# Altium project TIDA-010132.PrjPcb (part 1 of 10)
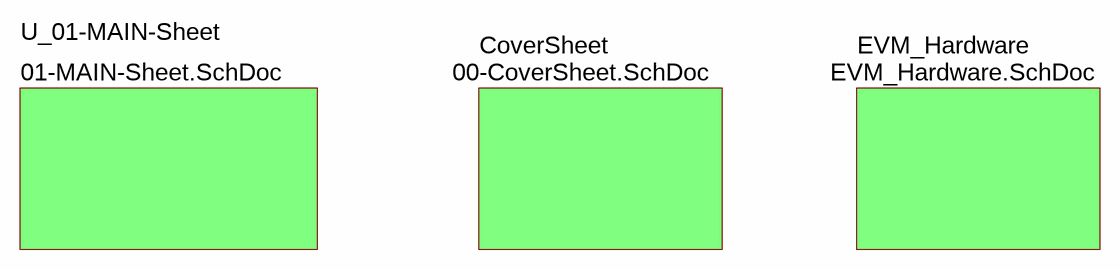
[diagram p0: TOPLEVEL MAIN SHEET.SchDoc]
CopyrightYear: 2018; PCB_Layout: Avinash; PCB_Rev: E1; PRJ_Customer: Public Release; PRJ_Engineer: Sankar Sadasivam; PRJ_Number: TIDA-010132; PRJ_Title: TIDA-010132; SCH_Rev: E1; TechSupport: http://www.ti.com/support; TID: 010132
32 sheets, 1754 parts. Net scope: flat (ports and power ports of the same name join across sheets).
Board file: TIDA-010132.PcbDoc
Sheets:
  TOPLEVEL MAIN SHEET.SchDoc
    U_01-MAIN-Sheet = 01-MAIN-Sheet.SchDoc
      FMC INTERFACE SHEET = FMC INTERFACE SHEET.SchDoc
      AFE1 = AFE1.SchDoc
        AFE1-RX-INPUTS. = AFE1-RX-INPUTS.SchDoc
        AFE1-TX-OUTPUTS = AFE1-TX-OUTPUTS.SchDoc
        AFE1-LMX2594 = AFE1-LMX2594.SchDoc
        AFE1-POWER = AFE1-POWER.SchDoc
        AFE1-SERDES = AFE1-SERDES.SchDoc
        AFE1-RX-TX-INTERFACE. = AFE1-RX-TX-INTERFACE.SchDoc
        AFE1-GROUND = AFE1-GROUND.SchDoc
        AFE1-PROGRAMMING INTERFACE = AFE1-PROGRAMMING INTERFACE.SchDoc
        AFE1-GPIOs = AFE1-GPIOs.SchDoc
      CLOCK MAIN = CLOCK MAIN SHEET.SchDoc
        CLOCK MAIN POWER = CLOCK MAIN POWER.SchDoc
        CLOCK BUFFER = CLOCK BUFFER.SchDoc
      POWER TREE. = POWER TREE.SchDoc
        POWER MAIN SHEET1 = POWER MAIN SHEET1.SchDoc
        POWER MAIN SHEET2 = POWER MAIN SHEET2.SchDoc
      USB INTERFACE = USB INTERFACE SHEET.SchDoc
      AFE2 = AFE2.SchDoc
        AFE2-SERDES = AFE2-SERDES.SchDoc
        AFE2-PROGRAMMING INTERFACE = AFE2-PROGRAMMING INTERFACE.SchDoc
        AFE2-GPIOs = AFE2-GPIOs.SchDoc
        AFE2-RX-INPUTS = AFE2-RX-INPUTS.SchDoc
        AFE2-TX-OUTPUTS = AFE2-TX-OUTPUTS.SchDoc
        AFE2-LMX2594 = AFE2-LMX2594.SchDoc
        AFE2-POWER = AFE2-POWER.SchDoc
        AFE2-RX-TX-INTERFACE = AFE2-RX-TX-INTERFACE.SchDoc
        AFE2-GROUND = AFE2-GROUND.SchDoc
    CoverSheet = 00-CoverSheet.SchDoc
    EVM_Hardware = EVM_Hardware.SchDoc

## Sheet TOPLEVEL MAIN SHEET.SchDoc
size 431 x 279 mm; Date: Not shown in title block; ApprovedBy: Not shown in title block; CheckedBy: Not shown in title block; Author: Not shown in title block; CompanyName: Not shown in title block; DrawnBy: Avinash N; Engineer: Not shown in title block; Organization: Not shown in title block; Address1: Not shown in title block; Address2: Not shown in title block; Address3: Not shown in title block; Address4: Not shown in title block; DocumentNumber: 1; Revision: Use project parameter SCH_Rev; SheetNumber: 2; SheetTotal: 32; PageSetup: Record=PageOptions¦CenterHorizontal=True¦CenterVertical=True¦PrintScale=1.00¦XCorrection=1.00¦YCorrection=1.00¦PrintKind=0¦BorderSize=5000000¦LeftOffset=0¦BottomOffset=0¦Orientation=2¦PaperLength=1000¦PaperWidth=1000¦Scale=100¦PaperSource=15¦PrintQuality=600¦MediaType=1¦DitherType=10¦PaperKind=Letter¦PrintScaleMode=1

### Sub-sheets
CoverSheet = 00-CoverSheet.SchDoc: no entries
EVM_Hardware = EVM_Hardware.SchDoc: no entries
U_01-MAIN-Sheet = 01-MAIN-Sheet.SchDoc: no entries

## Sheet 01-MAIN-Sheet.SchDoc
size 558 x 431 mm; Date: Not shown in title block; ApprovedBy: Not shown in title block; CheckedBy: Not shown in title block; Author: Not shown in title block; CompanyName: Not shown in title block; DrawnBy: Avinash N; Engineer: Not shown in title block; Organization: Not shown in title block; Address1: Not shown in title block; Address2: Not shown in title block; Address3: Not shown in title block; Address4: Not shown in title block; DocumentNumber: 1; Revision: Use project parameter SCH_Rev; SheetNumber: 3; SheetTotal: 32; PageSetup: Record=PageOptions¦CenterHorizontal=True¦CenterVertical=True¦PrintScale=1.00¦XCorrection=1.00¦YCorrection=1.00¦PrintKind=0¦BorderSize=5000000¦LeftOffset=0¦BottomOffset=0¦Orientation=2¦PaperLength=1000¦PaperWidth=1000¦Scale=100¦PaperSource=15¦PrintQuality=600¦MediaType=1¦DitherType=10¦PaperKind=Letter¦PrintScaleMode=1
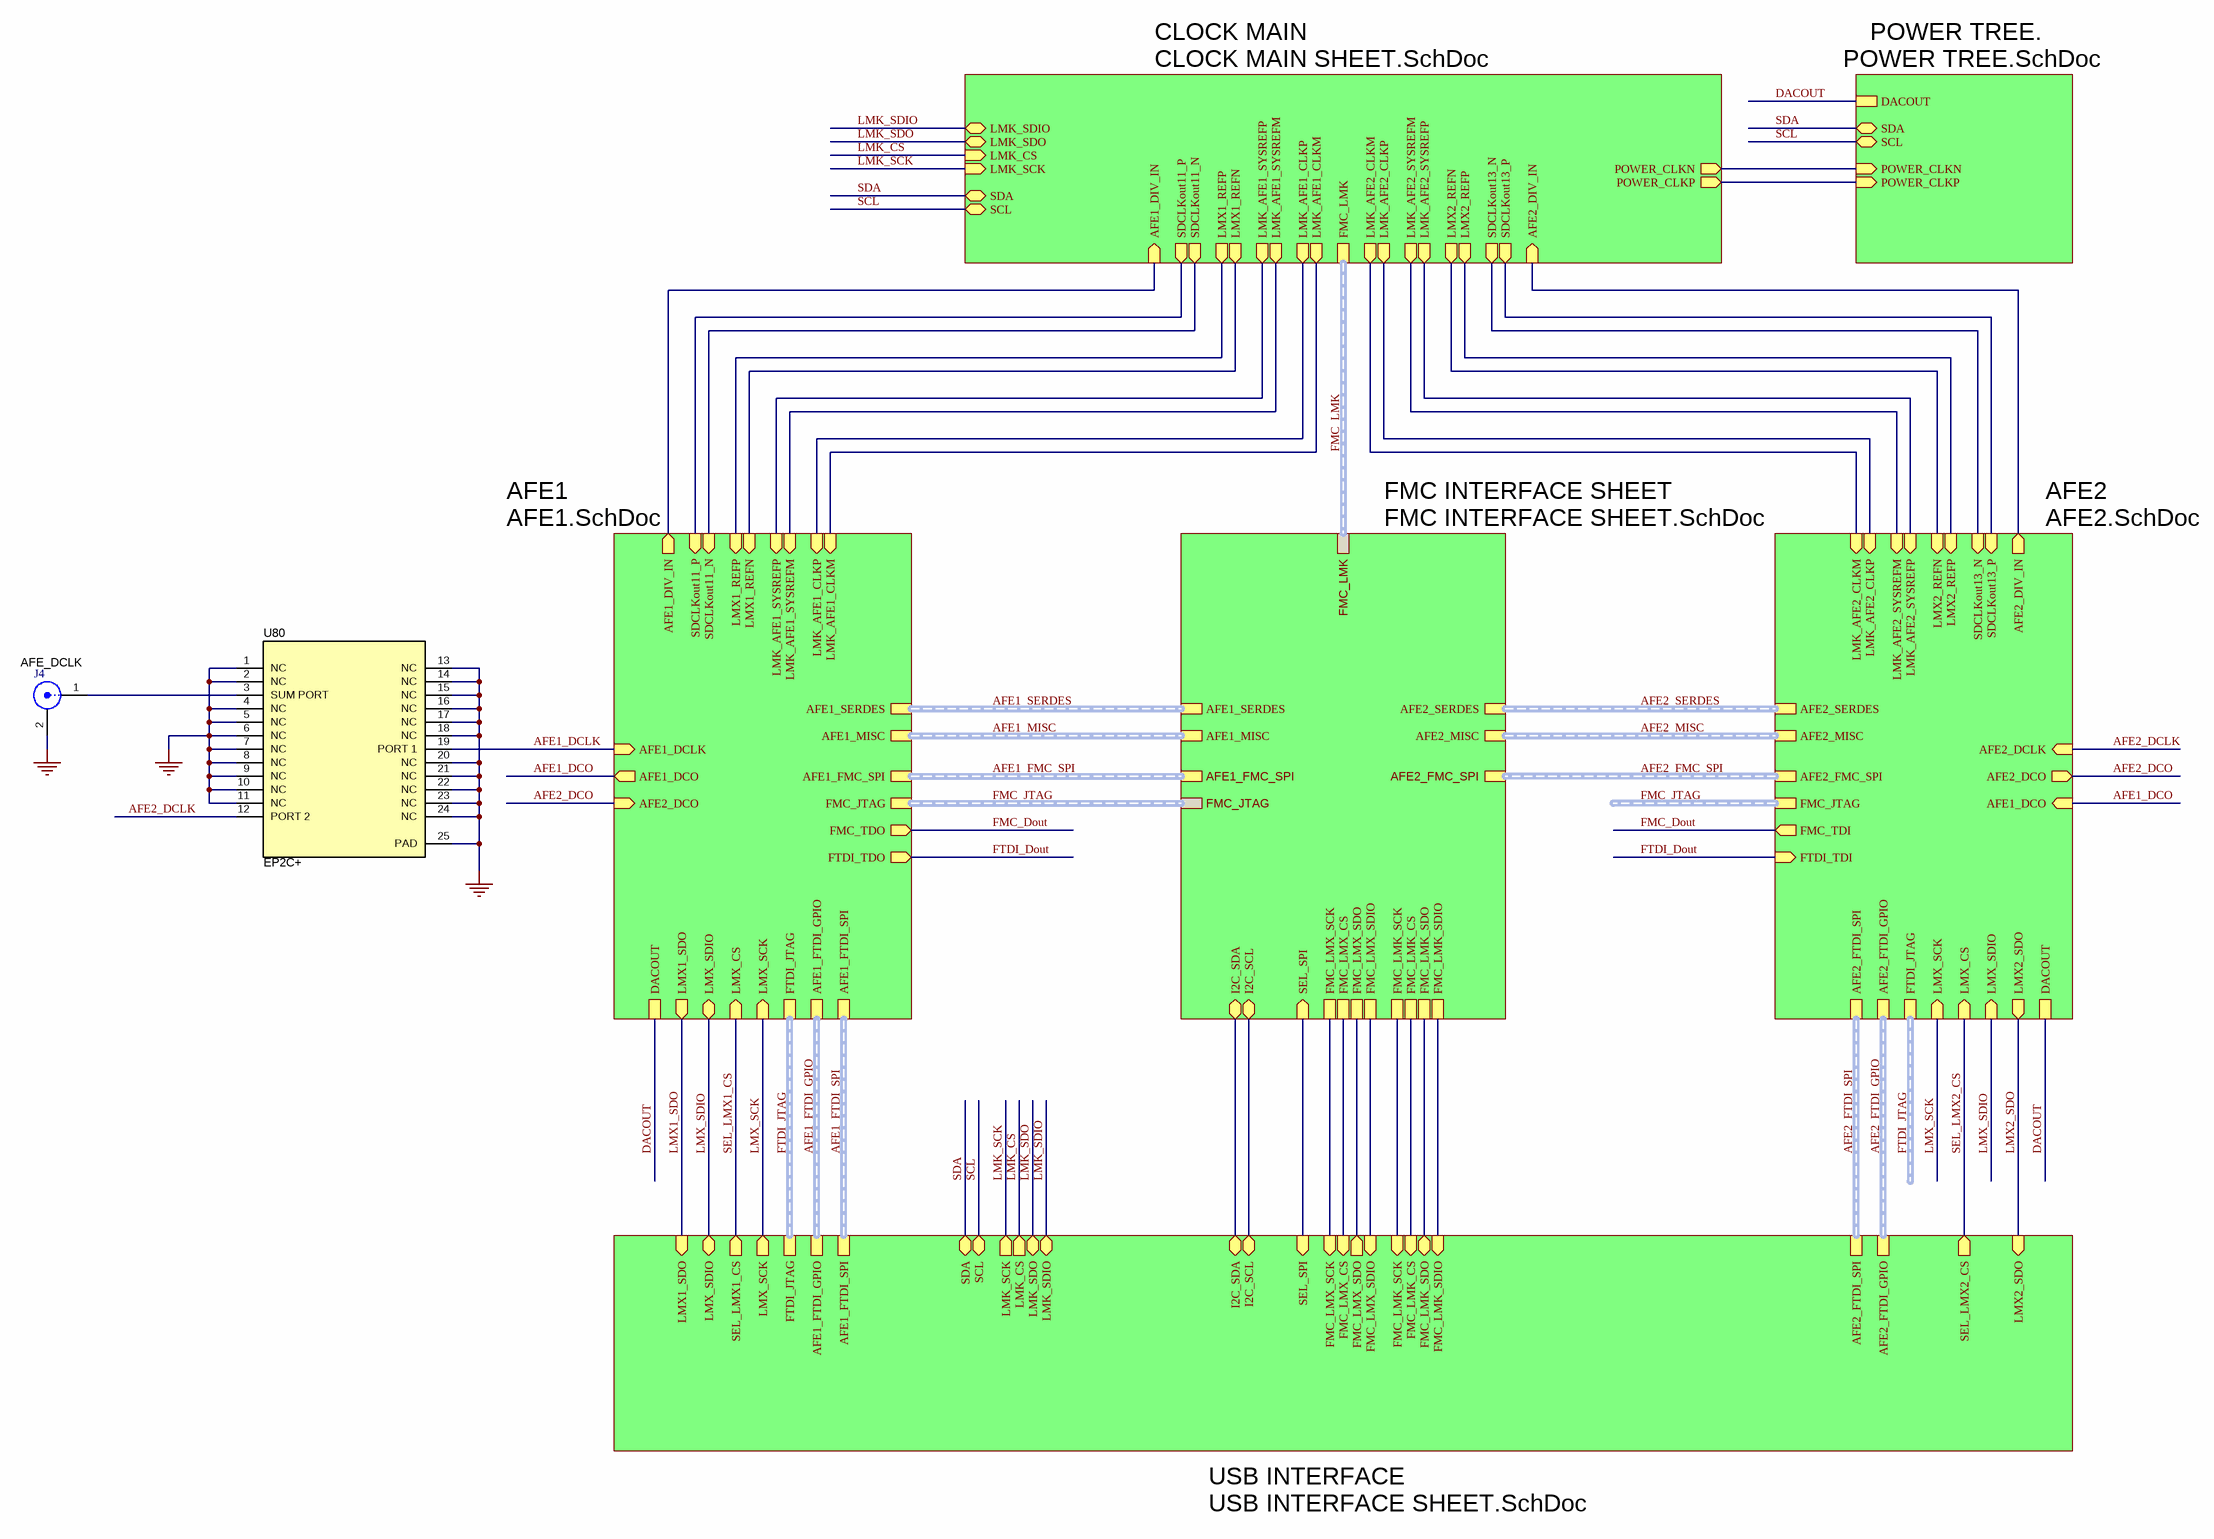
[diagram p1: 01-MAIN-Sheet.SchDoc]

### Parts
J4  AFE_DCLK  [Molex_0853050232]
U80  EP2C+  [DG1847]

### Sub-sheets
AFE1 = AFE1.SchDoc: AFE1_FTDI_SPI (harness AFE1_FTDI_SPI), AFE1_FTDI_GPIO (harness AFE1_FTDI_GPIO), FTDI_JTAG (harness FTDI_JTAG), FMC_JTAG (harness FMC_JTAG), LMX_CS (in), LMX_SCK (in), LMX1_SDO (out), DACOUT, AFE1_FMC_SPI (harness AFE1_FMC_SPI), FTDI_TDO (out), FMC_TDO (out), AFE1_SERDES (harness AFE1_SERDES), AFE1_MISC (harness AFE1_MISC), LMX_SDIO (bidir), LMK_AFE1_CLKP (in), LMK_AFE1_CLKM (in), LMK_AFE1_SYSREFP (in), LMK_AFE1_SYSREFM (in), LMX1_REFN (in), LMX1_REFP (in), SDCLKout11_P (in), SDCLKout11_N (in), AFE1_DIV_IN (out), AFE1_DCLK (in), AFE2_DCO (in), AFE1_DCO (out)
AFE2 = AFE2.SchDoc: AFE2_FTDI_GPIO (harness AFE2_FTDI_GPIO), FMC_JTAG (harness FMC_JTAG), AFE2_FTDI_SPI (harness AFE2_FTDI_SPI), FTDI_JTAG (harness FTDI_JTAG), LMX_SCK (in), LMX_CS (in), LMX_SDIO (in), DACOUT, AFE2_FMC_SPI (harness AFE2_FMC_SPI), LMX2_SDO (out), FTDI_TDI (in), AFE2_MISC (harness AFE2_MISC), AFE2_SERDES (harness AFE2_SERDES), FMC_TDI (out), LMK_AFE2_CLKM (in), LMK_AFE2_CLKP (in), LMK_AFE2_SYSREFM (in), LMK_AFE2_SYSREFP (in), LMX2_REFP (in), LMX2_REFN (in), SDCLKout13_P (in), SDCLKout13_N (in), AFE2_DIV_IN (out), AFE2_DCLK (in), AFE2_DCO (out), AFE1_DCO (in)
CLOCK MAIN = CLOCK MAIN SHEET.SchDoc: AFE1_DIV_IN (in), AFE2_DIV_IN (in), FMC_LMK (harness FMC_LMK), SDA (bidir), SCL (bidir), LMK_SCK (in), LMK_CS (in), LMK_SDIO (bidir), LMK_SDO (bidir), POWER_CLKN (out), POWER_CLKP (out), LMK_AFE1_CLKM (out), LMK_AFE1_CLKP (out), LMX1_REFP (out), LMX1_REFN (out), SDCLKout11_N (out), SDCLKout11_P (out), LMK_AFE2_CLKM (out), LMK_AFE2_CLKP (out), LMK_AFE2_SYSREFP (out), LMK_AFE2_SYSREFM (out), LMX2_REFN (out), LMX2_REFP (out), SDCLKout13_P (out), SDCLKout13_N (out), LMK_AFE1_SYSREFM (out), LMK_AFE1_SYSREFP (out)
FMC INTERFACE SHEET = FMC INTERFACE SHEET.SchDoc: FMC_JTAG (harness FMC_JTAG), FMC_LMK (harness FMC_LMK), AFE1_FMC_SPI (harness AFE1_FMC_SPI), AFE2_FMC_SPI (harness AFE2_FMC_SPI), AFE1_MISC (harness AFE1_MISC), AFE1_SERDES (harness AFE1_SERDES), AFE2_SERDES (harness AFE2_SERDES), AFE2_MISC (harness AFE2_MISC), I2C_SDA (bidir), I2C_SCL (bidir), FMC_LMX_SCK, FMC_LMX_SDIO, FMC_LMX_CS, FMC_LMK_SCK, FMC_LMK_SDO, FMC_LMK_SDIO, FMC_LMK_CS, FMC_LMX_SDO, SEL_SPI (in)
POWER TREE. = POWER TREE.SchDoc: DACOUT, POWER_CLKN (in), POWER_CLKP (in), SDA (bidir), SCL (bidir)
USB INTERFACE = USB INTERFACE SHEET.SchDoc: FMC_LMK_SCK (in), SDA (bidir), SCL (bidir), LMX_SCK (out), FMC_LMX_SDIO (in), LMX_SDIO (bidir), FMC_LMX_CS (in), FMC_LMX_SCK (in), LMX2_SDO (in), LMX1_SDO (in), FMC_LMX_SDO (out), AFE2_FTDI_SPI (harness AFE2_FTDI_SPI), AFE1_FTDI_SPI (harness AFE1_FTDI_SPI), FTDI_JTAG (harness FTDI_JTAG), AFE1_FTDI_GPIO (harness AFE1_FTDI_GPIO), AFE2_FTDI_GPIO (harness AFE2_FTDI_GPIO), LMK_CS (out), LMK_SDIO (bidir), LMK_SDO (bidir), LMK_SCK (out), FMC_LMK_CS (in), FMC_LMK_SDIO (in), FMC_LMK_SDO (bidir), I2C_SCL (bidir), I2C_SDA (bidir), SEL_LMX2_CS (out), SEL_SPI (in), SEL_LMX1_CS (out)

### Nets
GND: J4.2 U80.1(NC) U80.2(NC) U80.4(NC) U80.5(NC) U80.6(NC) U80.7(NC) U80.8(NC) U80.9(NC) U80.10(NC) U80.11(NC) U80.13(NC) U80.14(NC) U80.15(NC) U80.16(NC) U80.17(NC) U80.18(NC) U80.20(NC) U80.21(NC) U80.22(NC) U80.23(NC) U80.24(NC) U80.25(PAD)
AFE1_DCLK: U80.19(PORT_1) ; sheet AFE1/AFE1_DCLK
AFE1_DCO: sheet AFE1/AFE1_DCO, sheet AFE2/AFE1_DCO
AFE2_DCLK: U80.12(PORT_2) ; sheet AFE2/AFE2_DCLK
AFE2_DCO: sheet AFE1/AFE2_DCO, sheet AFE2/AFE2_DCO
DACOUT: sheet AFE1/DACOUT, sheet POWER TREE./DACOUT, sheet AFE2/DACOUT
FMC_Dout: sheet AFE1/FMC_TDO, sheet AFE2/FMC_TDI
FTDI_Dout: sheet AFE1/FTDI_TDO, sheet AFE2/FTDI_TDI
LMK_CS: sheet CLOCK MAIN/LMK_CS, sheet USB INTERFACE/LMK_CS
LMK_SCK: sheet CLOCK MAIN/LMK_SCK, sheet USB INTERFACE/LMK_SCK
LMK_SDIO: sheet CLOCK MAIN/LMK_SDIO, sheet USB INTERFACE/LMK_SDIO
LMK_SDO: sheet CLOCK MAIN/LMK_SDO, sheet USB INTERFACE/LMK_SDO
LMX1_SDO: sheet AFE1/LMX1_SDO, sheet USB INTERFACE/LMX1_SDO
LMX2_SDO: sheet USB INTERFACE/LMX2_SDO, sheet AFE2/LMX2_SDO
LMX_SCK: sheet AFE1/LMX_SCK, sheet USB INTERFACE/LMX_SCK, sheet AFE2/LMX_SCK
LMX_SDIO: sheet AFE1/LMX_SDIO, sheet USB INTERFACE/LMX_SDIO, sheet AFE2/LMX_SDIO
SCL: sheet CLOCK MAIN/SCL, sheet POWER TREE./SCL, sheet USB INTERFACE/SCL
SDA: sheet CLOCK MAIN/SDA, sheet POWER TREE./SDA, sheet USB INTERFACE/SDA
SEL_LMX1_CS: sheet AFE1/LMX_CS, sheet USB INTERFACE/SEL_LMX1_CS
SEL_LMX2_CS: sheet USB INTERFACE/SEL_LMX2_CS, sheet AFE2/LMX_CS
NetJ4_1: J4.1 U80.3(SUM_PORT)
(unnamed): sheet FMC INTERFACE SHEET/I2C_SDA, sheet USB INTERFACE/I2C_SDA
(unnamed): sheet FMC INTERFACE SHEET/I2C_SCL, sheet USB INTERFACE/I2C_SCL  [a separate net that carries the same name]
(unnamed): sheet FMC INTERFACE SHEET/FMC_LMX_SCK, sheet USB INTERFACE/FMC_LMX_SCK  [a separate net that carries the same name]
(unnamed): sheet FMC INTERFACE SHEET/FMC_LMX_SDIO, sheet USB INTERFACE/FMC_LMX_SDIO  [a separate net that carries the same name]
(unnamed): sheet FMC INTERFACE SHEET/FMC_LMX_CS, sheet USB INTERFACE/FMC_LMX_CS  [a separate net that carries the same name]
(unnamed): sheet FMC INTERFACE SHEET/FMC_LMK_SCK, sheet USB INTERFACE/FMC_LMK_SCK  [a separate net that carries the same name]
(unnamed): sheet FMC INTERFACE SHEET/FMC_LMK_SDO, sheet USB INTERFACE/FMC_LMK_SDO  [a separate net that carries the same name]
(unnamed): sheet FMC INTERFACE SHEET/FMC_LMK_SDIO, sheet USB INTERFACE/FMC_LMK_SDIO  [a separate net that carries the same name]
(unnamed): sheet FMC INTERFACE SHEET/FMC_LMK_CS, sheet USB INTERFACE/FMC_LMK_CS  [a separate net that carries the same name]
(unnamed): sheet FMC INTERFACE SHEET/FMC_LMX_SDO, sheet USB INTERFACE/FMC_LMX_SDO  [a separate net that carries the same name]
(unnamed): sheet FMC INTERFACE SHEET/SEL_SPI, sheet USB INTERFACE/SEL_SPI  [a separate net that carries the same name]
(unnamed): sheet AFE1/LMK_AFE1_CLKP, sheet CLOCK MAIN/LMK_AFE1_CLKP  [a separate net that carries the same name]
(unnamed): sheet AFE1/LMK_AFE1_CLKM, sheet CLOCK MAIN/LMK_AFE1_CLKM  [a separate net that carries the same name]
(unnamed): sheet AFE1/LMK_AFE1_SYSREFP, sheet CLOCK MAIN/LMK_AFE1_SYSREFP  [a separate net that carries the same name]
(unnamed): sheet AFE1/LMK_AFE1_SYSREFM, sheet CLOCK MAIN/LMK_AFE1_SYSREFM  [a separate net that carries the same name]
(unnamed): sheet AFE1/LMX1_REFN, sheet CLOCK MAIN/LMX1_REFN  [a separate net that carries the same name]
(unnamed): sheet AFE1/LMX1_REFP, sheet CLOCK MAIN/LMX1_REFP  [a separate net that carries the same name]
(unnamed): sheet AFE1/SDCLKout11_P, sheet CLOCK MAIN/SDCLKout11_P  [a separate net that carries the same name]
(unnamed): sheet AFE1/SDCLKout11_N, sheet CLOCK MAIN/SDCLKout11_N  [a separate net that carries the same name]
(unnamed): sheet AFE1/AFE1_DIV_IN, sheet CLOCK MAIN/AFE1_DIV_IN  [a separate net that carries the same name]
(unnamed): sheet CLOCK MAIN/AFE2_DIV_IN, sheet AFE2/AFE2_DIV_IN  [a separate net that carries the same name]
(unnamed): sheet CLOCK MAIN/POWER_CLKN, sheet POWER TREE./POWER_CLKN  [a separate net that carries the same name]
(unnamed): sheet CLOCK MAIN/POWER_CLKP, sheet POWER TREE./POWER_CLKP  [a separate net that carries the same name]
(unnamed): sheet CLOCK MAIN/LMK_AFE2_CLKM, sheet AFE2/LMK_AFE2_CLKM  [a separate net that carries the same name]
(unnamed): sheet CLOCK MAIN/LMK_AFE2_CLKP, sheet AFE2/LMK_AFE2_CLKP  [a separate net that carries the same name]
(unnamed): sheet CLOCK MAIN/LMK_AFE2_SYSREFP, sheet AFE2/LMK_AFE2_SYSREFP  [a separate net that carries the same name]
(unnamed): sheet CLOCK MAIN/LMK_AFE2_SYSREFM, sheet AFE2/LMK_AFE2_SYSREFM  [a separate net that carries the same name]
(unnamed): sheet CLOCK MAIN/LMX2_REFN, sheet AFE2/LMX2_REFN  [a separate net that carries the same name]
(unnamed): sheet CLOCK MAIN/LMX2_REFP, sheet AFE2/LMX2_REFP  [a separate net that carries the same name]
(unnamed): sheet CLOCK MAIN/SDCLKout13_P, sheet AFE2/SDCLKout13_P  [a separate net that carries the same name]
(unnamed): sheet CLOCK MAIN/SDCLKout13_N, sheet AFE2/SDCLKout13_N  [a separate net that carries the same name]

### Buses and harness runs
harness AFE1_FMC_SPI = sheet AFE1/AFE1_FMC_SPI = sheet FMC INTERFACE SHEET/AFE1_FMC_SPI
harness AFE1_FTDI_GPIO = sheet AFE1/AFE1_FTDI_GPIO = sheet USB INTERFACE/AFE1_FTDI_GPIO
harness AFE1_FTDI_SPI = sheet AFE1/AFE1_FTDI_SPI = sheet USB INTERFACE/AFE1_FTDI_SPI
harness AFE1_MISC = sheet AFE1/AFE1_MISC = sheet FMC INTERFACE SHEET/AFE1_MISC
harness AFE1_SERDES = sheet AFE1/AFE1_SERDES = sheet FMC INTERFACE SHEET/AFE1_SERDES
harness AFE2_FMC_SPI = sheet AFE2/AFE2_FMC_SPI = sheet FMC INTERFACE SHEET/AFE2_FMC_SPI
harness AFE2_FTDI_GPIO = sheet AFE2/AFE2_FTDI_GPIO = sheet USB INTERFACE/AFE2_FTDI_GPIO
harness AFE2_FTDI_SPI = sheet AFE2/AFE2_FTDI_SPI = sheet USB INTERFACE/AFE2_FTDI_SPI
harness AFE2_MISC = sheet AFE2/AFE2_MISC = sheet FMC INTERFACE SHEET/AFE2_MISC
harness AFE2_SERDES = sheet AFE2/AFE2_SERDES = sheet FMC INTERFACE SHEET/AFE2_SERDES
harness FMC_JTAG = sheet AFE1/FMC_JTAG = sheet FMC INTERFACE SHEET/FMC_JTAG
harness FMC_JTAG = sheet AFE2/FMC_JTAG
harness FMC_LMK = sheet CLOCK MAIN/FMC_LMK = sheet FMC INTERFACE SHEET/FMC_LMK
harness FTDI_JTAG = sheet AFE1/FTDI_JTAG = sheet USB INTERFACE/FTDI_JTAG
harness FTDI_JTAG = sheet AFE2/FTDI_JTAG

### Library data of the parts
J4 = CMP-0077224-1: Plug, 50 Ohm, Straight, SMT; PartNumber: 0853050232; Manufacturer: Molex; Cert_UL: Y; ContactFinish: Gold; CT: False; Gender: Male; Voltage_V: 335V
U80 = CMP-0065468-1: Power Splitter/Combiner, 2 Way-0°, 50Ohm, 1800 to 12500 MHz; Manufacturer: Minicircuits; SizeZ_mm: 1.0; SizeX_mm: 4.0; SizeArea_mm2: 16.0; SizeAreaWB_mm2: 25.0

## Sheet FMC INTERFACE SHEET.SchDoc
size 558 x 431 mm; Date: Not shown in title block; ApprovedBy: Not shown in title block; CheckedBy: Not shown in title block; Author: Not shown in title block; CompanyName: Not shown in title block; DrawnBy: Avinash N; Engineer: Not shown in title block; Organization: Not shown in title block; Address1: Not shown in title block; Address2: Not shown in title block; Address3: Not shown in title block; Address4: Not shown in title block; DocumentNumber: 1; Revision: Use project parameter SCH_Rev; SheetNumber: 28; SheetTotal: 32; PageSetup: Record=PageOptions¦CenterHorizontal=True¦CenterVertical=True¦PrintScale=1.00¦XCorrection=1.00¦YCorrection=1.00¦PrintKind=0¦BorderSize=5000000¦LeftOffset=0¦BottomOffset=0¦Orientation=2¦PaperLength=1000¦PaperWidth=1000¦Scale=100¦PaperSource=15¦PrintQuality=600¦MediaType=1¦DitherType=10¦PaperKind=Letter¦PrintScaleMode=1
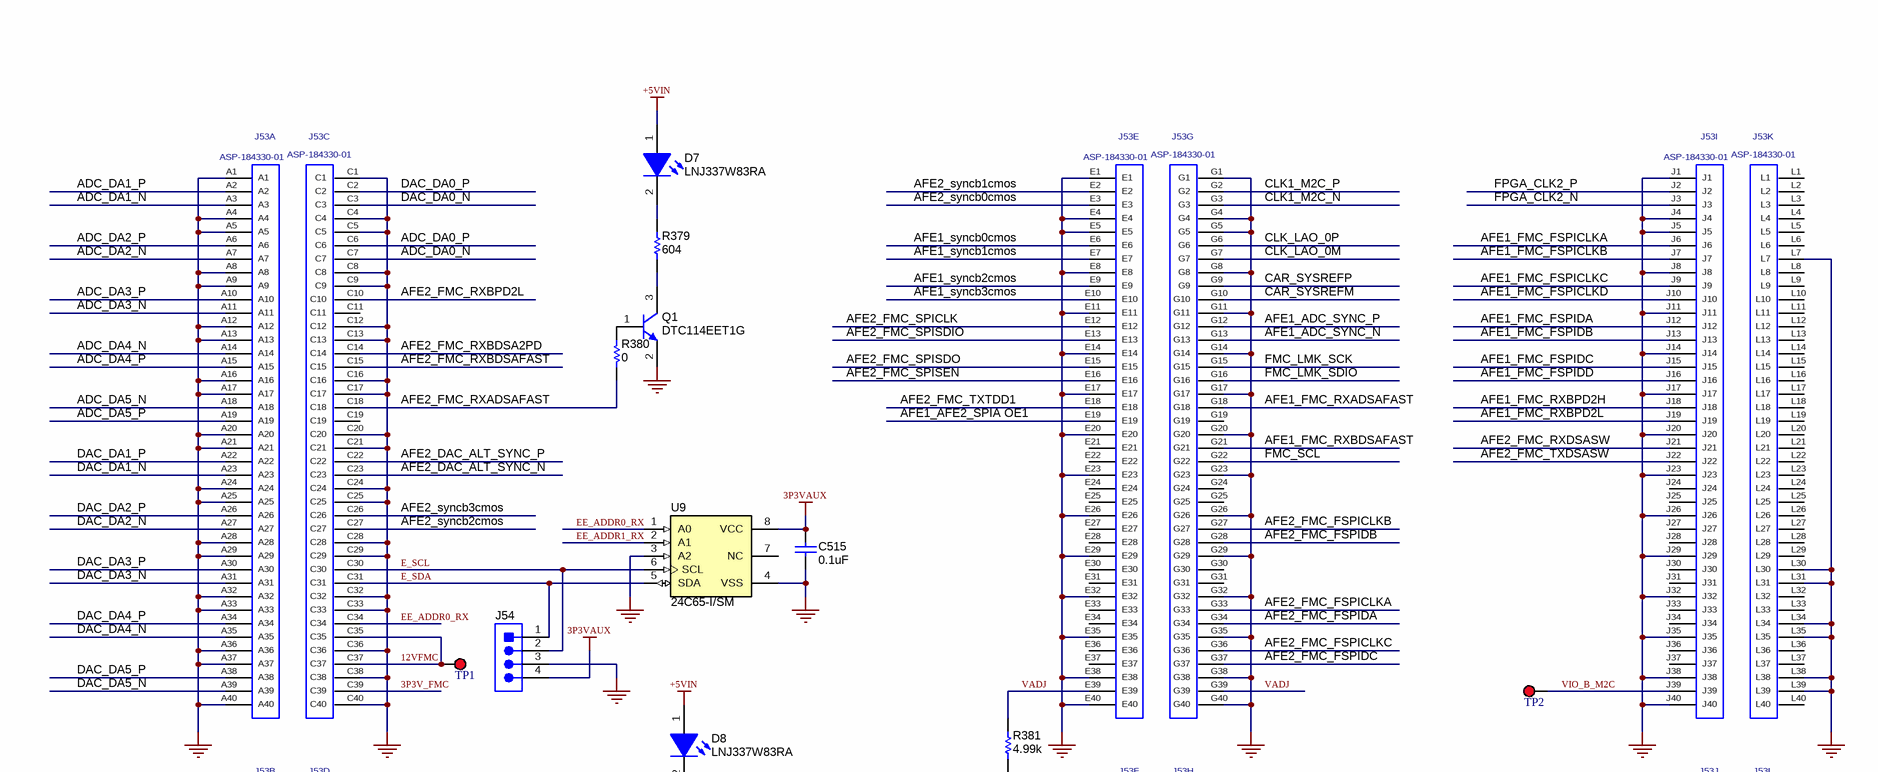
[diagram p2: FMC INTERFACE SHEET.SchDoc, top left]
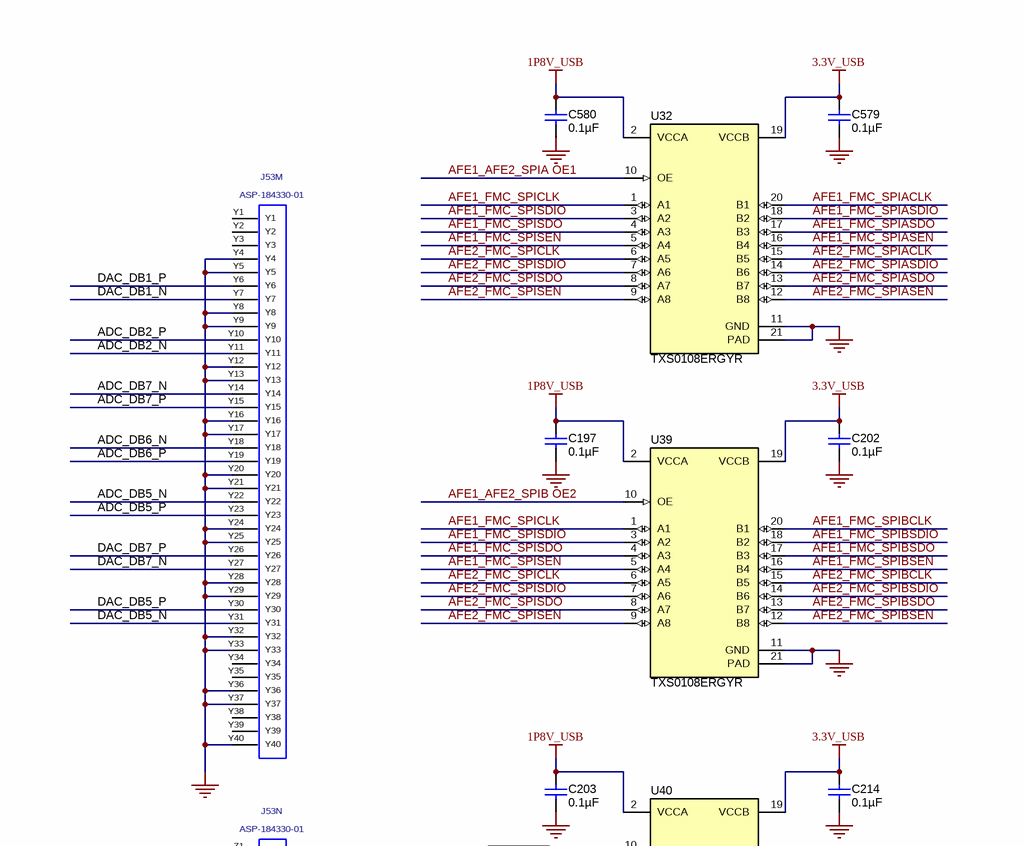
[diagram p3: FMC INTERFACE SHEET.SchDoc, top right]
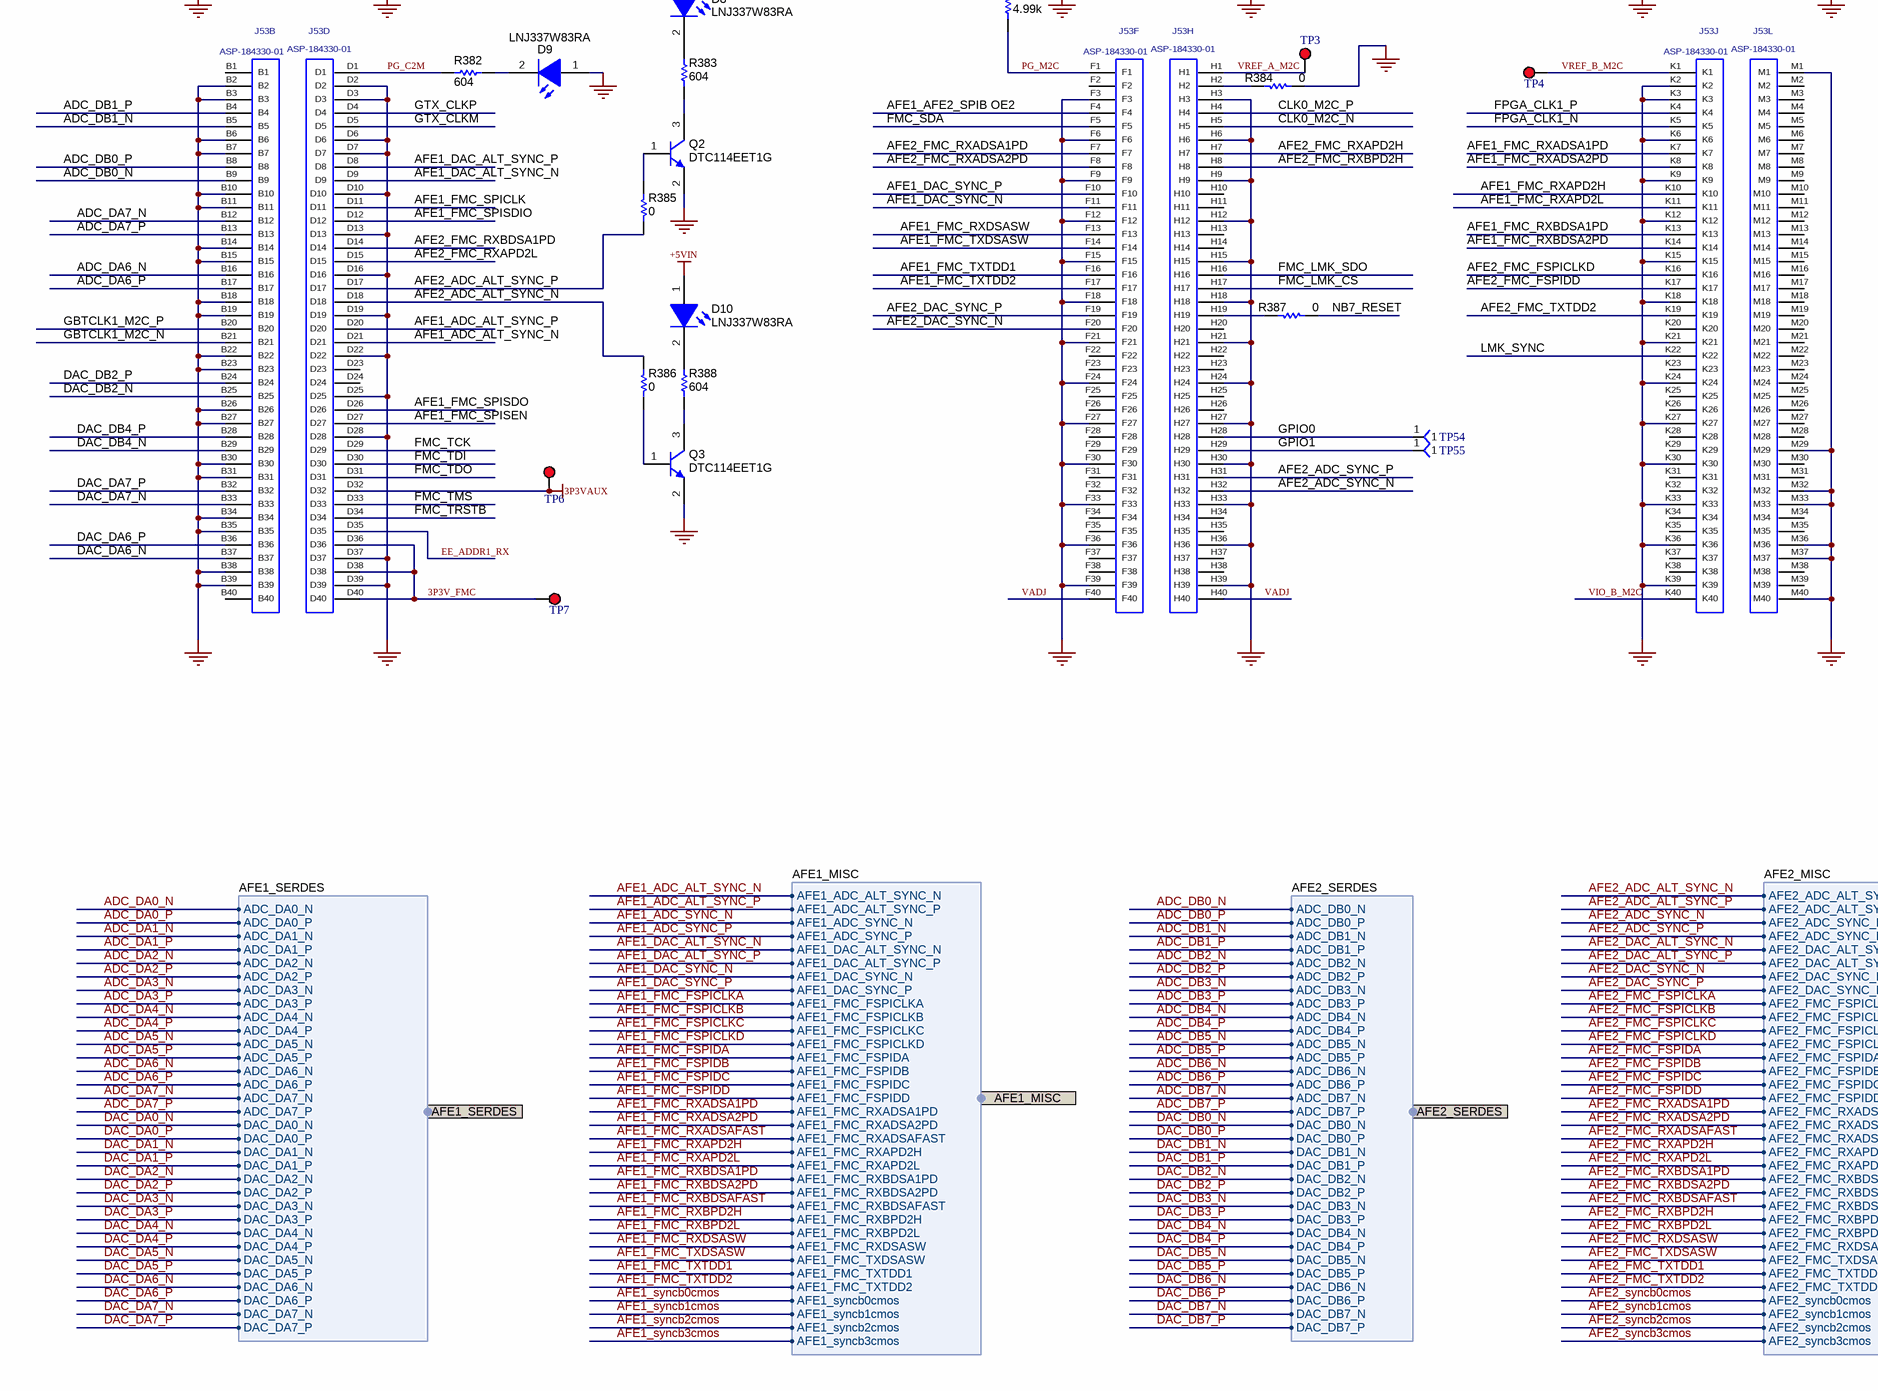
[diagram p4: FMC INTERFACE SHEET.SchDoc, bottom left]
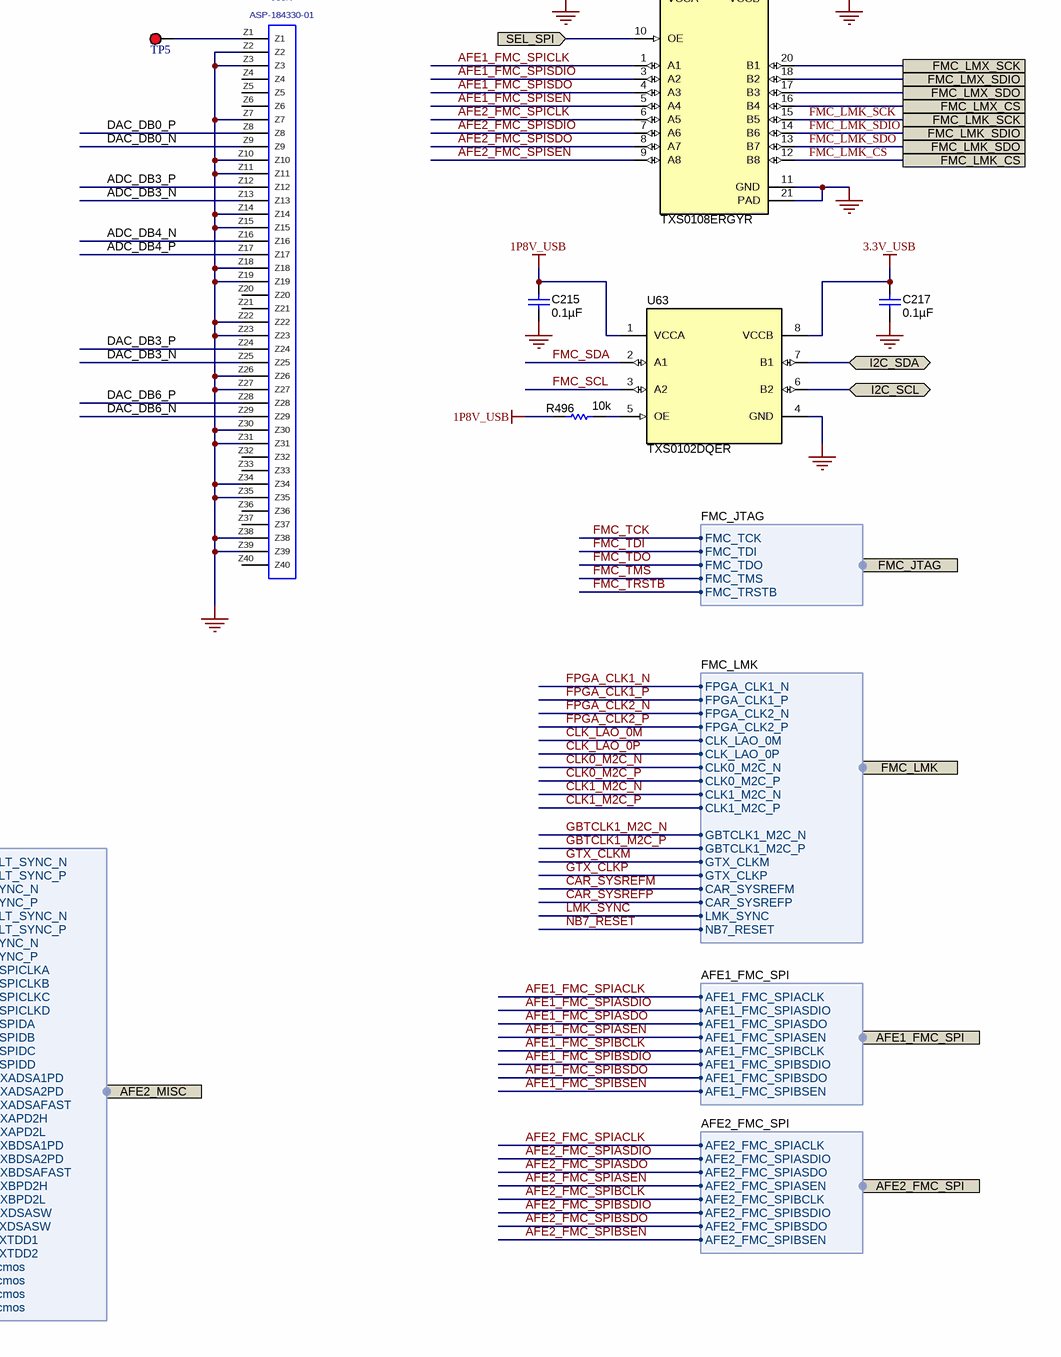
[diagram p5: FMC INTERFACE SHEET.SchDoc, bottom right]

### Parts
C197  ValueDisplayed: 0.1µF  [0603]  (hidden comment: C0603C104J3RACTU)
C202  ValueDisplayed: 0.1µF  [0603]  (hidden comment: C0603C104J3RACTU)
C203  ValueDisplayed: 0.1µF  [0603]  (hidden comment: C0603C104J3RACTU)
C214  ValueDisplayed: 0.1µF  [0603]  (hidden comment: C0603C104J3RACTU)
C215  ValueDisplayed: 0.1µF  [0603]  (hidden comment: C0603C104J3RACTU)
C217  ValueDisplayed: 0.1µF  [0603]  (hidden comment: C0603C104J3RACTU)
C515  ValueDisplayed: 0.1uF  [0402_065]  (hidden comment: 550L104KCAT)
C579  ValueDisplayed: 0.1µF  [0603]  (hidden comment: C0603C104J3RACTU)
C580  ValueDisplayed: 0.1µF  [0603]  (hidden comment: C0603C104J3RACTU)
D7  LNJ337W83RA  [LNJx37x8_Green]
D8  LNJ337W83RA  [LNJx37x8_Green]
D9  LNJ337W83RA  [LNJx37x8_Green]
D10  LNJ337W83RA  [LNJx37x8_Green]
J53  ASP-184330-01  [ASP-184330-01]  (parts A,B,C,D,E,F,G,H,I,J,K,L,M,N of 14)
J54  342-10-104-00-591000  [Mill-Max_342-xx-104-00-591000]  (value not drawn)
Q1  DTC114EET1G  [SOT-416]
Q2  DTC114EET1G  [SOT-416]
Q3  DTC114EET1G  [SOT-416]
R379  ValueDisplayed: 604  [0603]  (hidden comment: RC0603FR-07604RL)
R380  ValueDisplayed: 0  [0402]  (hidden comment: ERJ-2GE0R00X)
R381  ValueDisplayed: 4.99k  [0603]  (hidden comment: CRCW06034K99FKEA)
R382  ValueDisplayed: 604  [0603]  (hidden comment: RC0603FR-07604RL)
R383  ValueDisplayed: 604  [0603]  (hidden comment: RC0603FR-07604RL)
R384  ValueDisplayed: 0  [0402]  (hidden comment: ERJ-2GE0R00X)
R385  ValueDisplayed: 0  [0402]  (hidden comment: ERJ-2GE0R00X)
R386  ValueDisplayed: 0  [0402]  (hidden comment: ERJ-2GE0R00X)
R387  ValueDisplayed: 0  [0402]  (hidden comment: ERJ-2GE0R00X)
R388  ValueDisplayed: 604  [0603]  (hidden comment: RC0603FR-07604RL)
R496  ValueDisplayed: 10k  [0603]  (hidden comment: CRCW060310K0JNEA)
TP1  5000  [Keystone5000]  (value not drawn)
TP2  5000  [Keystone5000]  (value not drawn)
TP3  5000  [Keystone5000]  (value not drawn)
TP4  5000  [Keystone5000]  (value not drawn)
TP5  5000  [Keystone5000]  (value not drawn)
TP6  5000  [Keystone5000]  (value not drawn)
TP7  5000  [Keystone5000]  (value not drawn)
TP54  TP-025-SMT  [TP_25MIL-SMT]  (value not drawn)
TP55  TP-025-SMT  [TP_25MIL-SMT]  (value not drawn)
U9  24C65-I/SM  [SOIC127P800X216-8N]
U32  TXS0108ERGYR  [RGY0020A]
U39  TXS0108ERGYR  [RGY0020A]
U40  TXS0108ERGYR  [RGY0020A]
U63  TXS0102DQER  [DQE0008A]

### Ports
AFE1_FMC_SPI (harness AFE1_FMC_SPI), AFE1_MISC (harness AFE1_MISC), AFE1_SERDES (harness AFE1_SERDES), AFE2_FMC_SPI (harness AFE2_FMC_SPI), AFE2_MISC (harness AFE2_MISC), AFE2_SERDES (harness AFE2_SERDES), FMC_JTAG (harness FMC_JTAG), FMC_LMK (harness FMC_LMK), FMC_LMK_CS, FMC_LMK_SCK, FMC_LMK_SDIO, FMC_LMK_SDO, FMC_LMX_CS, FMC_LMX_SCK, FMC_LMX_SDIO, FMC_LMX_SDO, I2C_SCL (bidir), I2C_SDA (bidir), SEL_SPI (in)

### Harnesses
AFE1_MISC: AFE1_ADC_ALT_SYNC_N, AFE1_ADC_ALT_SYNC_P, AFE1_ADC_SYNC_N, AFE1_ADC_SYNC_P, AFE1_DAC_ALT_SYNC_N, AFE1_DAC_ALT_SYNC_P, AFE1_DAC_SYNC_N, AFE1_DAC_SYNC_P, AFE1_FMC_FSPICLKA, AFE1_FMC_FSPICLKB, AFE1_FMC_FSPICLKC, AFE1_FMC_FSPICLKD, AFE1_FMC_FSPIDA, AFE1_FMC_FSPIDB, AFE1_FMC_FSPIDC, AFE1_FMC_FSPIDD, AFE1_FMC_RXADSA1PD, AFE1_FMC_RXADSA2PD, AFE1_FMC_RXADSAFAST, AFE1_FMC_RXAPD2H, AFE1_FMC_RXAPD2L, AFE1_FMC_RXBDSA1PD, AFE1_FMC_RXBDSA2PD, AFE1_FMC_RXBDSAFAST, AFE1_FMC_RXBPD2H, AFE1_FMC_RXBPD2L, AFE1_FMC_RXDSASW, AFE1_FMC_TXDSASW, AFE1_FMC_TXTDD1, AFE1_FMC_TXTDD2, AFE1_syncb0cmos, AFE1_syncb1cmos, AFE1_syncb2cmos, AFE1_syncb3cmos
AFE2_SERDES: ADC_DB0_N, ADC_DB0_P, ADC_DB1_N, ADC_DB1_P, ADC_DB2_N, ADC_DB2_P, ADC_DB3_N, ADC_DB3_P, ADC_DB4_N, ADC_DB4_P, ADC_DB5_N, ADC_DB5_P, ADC_DB6_N, ADC_DB6_P, ADC_DB7_N, ADC_DB7_P, DAC_DB0_N, DAC_DB0_P, DAC_DB1_N, DAC_DB1_P, DAC_DB2_N, DAC_DB2_P, DAC_DB3_N, DAC_DB3_P, DAC_DB4_N, DAC_DB4_P, DAC_DB5_N, DAC_DB5_P, DAC_DB6_N, DAC_DB6_P, DAC_DB7_N, DAC_DB7_P
AFE1_SERDES: ADC_DA0_N, ADC_DA0_P, ADC_DA1_N, ADC_DA1_P, ADC_DA2_N, ADC_DA2_P, ADC_DA3_N, ADC_DA3_P, ADC_DA4_N, ADC_DA4_P, ADC_DA5_N, ADC_DA5_P, ADC_DA6_N, ADC_DA6_P, ADC_DA7_N, ADC_DA7_P, DAC_DA0_N, DAC_DA0_P, DAC_DA1_N, DAC_DA1_P, DAC_DA2_N, DAC_DA2_P, DAC_DA3_N, DAC_DA3_P, DAC_DA4_N, DAC_DA4_P, DAC_DA5_N, DAC_DA5_P, DAC_DA6_N, DAC_DA6_P, DAC_DA7_N, DAC_DA7_P
AFE2_MISC: AFE2_ADC_ALT_SYNC_N, AFE2_ADC_ALT_SYNC_P, AFE2_ADC_SYNC_N, AFE2_ADC_SYNC_P, AFE2_DAC_ALT_SYNC_N, AFE2_DAC_ALT_SYNC_P, AFE2_DAC_SYNC_N, AFE2_DAC_SYNC_P, AFE2_FMC_FSPICLKA, AFE2_FMC_FSPICLKB, AFE2_FMC_FSPICLKC, AFE2_FMC_FSPICLKD, AFE2_FMC_FSPIDA, AFE2_FMC_FSPIDB, AFE2_FMC_FSPIDC, AFE2_FMC_FSPIDD, AFE2_FMC_RXADSA1PD, AFE2_FMC_RXADSA2PD, AFE2_FMC_RXADSAFAST, AFE2_FMC_RXAPD2H, AFE2_FMC_RXAPD2L, AFE2_FMC_RXBDSA1PD, AFE2_FMC_RXBDSA2PD, AFE2_FMC_RXBDSAFAST, AFE2_FMC_RXBPD2H, AFE2_FMC_RXBPD2L, AFE2_FMC_RXDSASW, AFE2_FMC_TXDSASW, AFE2_FMC_TXTDD1, AFE2_FMC_TXTDD2, AFE2_syncb0cmos, AFE2_syncb1cmos, AFE2_syncb2cmos, AFE2_syncb3cmos
FMC_JTAG: FMC_TCK, FMC_TDI, FMC_TDO, FMC_TMS, FMC_TRSTB
FMC_LMK: FPGA_CLK1_N, FPGA_CLK1_P, FPGA_CLK2_N, FPGA_CLK2_P, GBTCLK1_M2C_N, GBTCLK1_M2C_P, GTX_CLKM, GTX_CLKP, CAR_SYSREFM, CAR_SYSREFP, LMK_SYNC, NB7_RESET, CLK_LAO_0M, CLK_LAO_0P, CLK0_M2C_N, CLK0_M2C_P, CLK1_M2C_N, CLK1_M2C_P
AFE1_FMC_SPI: AFE1_FMC_SPIACLK, AFE1_FMC_SPIASDIO, AFE1_FMC_SPIASDO, AFE1_FMC_SPIASEN, AFE1_FMC_SPIBCLK, AFE1_FMC_SPIBSDIO, AFE1_FMC_SPIBSDO, AFE1_FMC_SPIBSEN
AFE2_FMC_SPI: AFE2_FMC_SPIACLK, AFE2_FMC_SPIASDIO, AFE2_FMC_SPIASDO, AFE2_FMC_SPIASEN, AFE2_FMC_SPIBCLK, AFE2_FMC_SPIBSDIO, AFE2_FMC_SPIBSDO, AFE2_FMC_SPIBSEN

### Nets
1P8V_USB: C197.2 C203.2 C215.2 C580.2 R496.2 U32.2(VCCA) U39.2(VCCA) U40.2(VCCA) U63.1(VCCA)
3.3V_USB: C202.2 C214.2 C217.2 C579.2 U32.19(VCCB) U39.19(VCCB) U40.19(VCCB) U63.8(VCCB)
3P3VAUX: C515.1 J53.D32 J54.4 TP6.1 U9.8(VCC)
+5VIN: D7.1(A) D8.1(A) D10.1(A)
GND: C197.1 C202.1 C203.1 C214.1 C215.1 C217.1 C515.2 C579.1 C580.1 D9.1(A) J53.A1 J53.A4 J53.A5 J53.A8 J53.A9 J53.A12 J53.A13 J53.A16 J53.A17 J53.A20 J53.A21 J53.A24 J53.A25 J53.A28 J53.A29 J53.A32 J53.A33 J53.A36 J53.A37 J53.A40 J53.B2 J53.B3 J53.B6 J53.B7 J53.B10 J53.B11 J53.B14 J53.B15 J53.B18 J53.B19 J53.B22 J53.B23 J53.B26 J53.B27 J53.B30 J53.B31 J53.B34 J53.B35 J53.B38 J53.B39 J53.C1 J53.C4 J53.C5 J53.C8 J53.C9 J53.C12 J53.C13 J53.C16 J53.C17 J53.C20 J53.C21 J53.C24 J53.C25 J53.C28 J53.C29 J53.C32 J53.C33 J53.C36 J53.C38 J53.C40 J53.D2 J53.D3 J53.D6 J53.D7 J53.D10 J53.D13 J53.D16 J53.D19 J53.D22 J53.D25 J53.D28 J53.D37 J53.D39 J53.E1 J53.E4 J53.E5 J53.E8 J53.E11 J53.E14 J53.E17 J53.E20 J53.E23 J53.E26 J53.E29 J53.E32 J53.E35 J53.E38 J53.E40 J53.F3 J53.F6 J53.F9 J53.F12 J53.F15 J53.F18 J53.F21 J53.F24 J53.F27 J53.F30 J53.F33 J53.F36 J53.F39 J53.G1 J53.G4 J53.G5 J53.G8 J53.G11 J53.G14 J53.G17 J53.G20 J53.G23 J53.G26 J53.G29 J53.G32 J53.G35 J53.G38 J53.G40 J53.H3 J53.H6 J53.H9 J53.H12 J53.H15 J53.H18 J53.H21 J53.H24 J53.H27 J53.H30 J53.H33 J53.H36 J53.H39 J53.J1 J53.J4 J53.J5 J53.J8 J53.J11 J53.J14 J53.J17 J53.J20 J53.J23 J53.J26 J53.J29 J53.J32 J53.J35 J53.J38 J53.J40 J53.K2 J53.K3 J53.K6 J53.K9 J53.K12 J53.K15 J53.K18 J53.K21 J53.K24 J53.K27 J53.K30 J53.K33 J53.K36 J53.K39 J53.L7 J53.L30 J53.L31 J53.L34 J53.L35 J53.L38 J53.L39 J53.M1 J53.M29 J53.M32 J53.M33 J53.M36 J53.M37 J53.M40 J53.Y4 J53.Y5 J53.Y8 J53.Y9 J53.Y12 J53.Y13 J53.Y16 J53.Y17 J53.Y20 J53.Y21 J53.Y24 J53.Y25 J53.Y28 J53.Y29 J53.Y32 J53.Y33 J53.Y36 J53.Y37 J53.Y40 J53.Z2 J53.Z3 J53.Z7 J53.Z10 J53.Z11 J53.Z14 J53.Z15 J53.Z18 J53.Z19 J53.Z22 J53.Z23 J53.Z26 J53.Z27 J53.Z30 J53.Z31 J53.Z34 J53.Z35 J53.Z38 J53.Z39 J54.3 Q1.2(E) Q2.2(E) Q3.2(E) R384.1 U9.3(A2) U9.4(VSS) U32.11(GND) U32.21(PAD) U39.11(GND) U39.21(PAD) U40.11(GND) U40.21(PAD) U63.4(GND)
3P3V_FMC: J53.C39 J53.D36 J53.D38 J53.D40 TP7.1
12VFMC: J53.C35 J53.C37 TP1.1
ADC_DA0_N: J53.C7 ; port AFE1_SERDES.ADC_DA0_N
ADC_DA0_P: J53.C6 ; port AFE1_SERDES.ADC_DA0_P
ADC_DA1_N: J53.A3 ; port AFE1_SERDES.ADC_DA1_N
ADC_DA1_P: J53.A2 ; port AFE1_SERDES.ADC_DA1_P
ADC_DA2_N: J53.A7 ; port AFE1_SERDES.ADC_DA2_N
ADC_DA2_P: J53.A6 ; port AFE1_SERDES.ADC_DA2_P
ADC_DA3_N: J53.A11 ; port AFE1_SERDES.ADC_DA3_N
ADC_DA3_P: J53.A10 ; port AFE1_SERDES.ADC_DA3_P
ADC_DA4_N: J53.A14 ; port AFE1_SERDES.ADC_DA4_N
ADC_DA4_P: J53.A15 ; port AFE1_SERDES.ADC_DA4_P
ADC_DA5_N: J53.A18 ; port AFE1_SERDES.ADC_DA5_N
ADC_DA5_P: J53.A19 ; port AFE1_SERDES.ADC_DA5_P
ADC_DA6_N: J53.B16 ; port AFE1_SERDES.ADC_DA6_N
ADC_DA6_P: J53.B17 ; port AFE1_SERDES.ADC_DA6_P
ADC_DA7_N: J53.B12 ; port AFE1_SERDES.ADC_DA7_N
ADC_DA7_P: J53.B13 ; port AFE1_SERDES.ADC_DA7_P
ADC_DB0_N: J53.B9 ; port AFE2_SERDES.ADC_DB0_N
ADC_DB0_P: J53.B8 ; port AFE2_SERDES.ADC_DB0_P
ADC_DB1_N: J53.B5 ; port AFE2_SERDES.ADC_DB1_N
ADC_DB1_P: J53.B4 ; port AFE2_SERDES.ADC_DB1_P
ADC_DB2_N: J53.Y11 ; port AFE2_SERDES.ADC_DB2_N
ADC_DB2_P: J53.Y10 ; port AFE2_SERDES.ADC_DB2_P
ADC_DB3_N: J53.Z13 ; port AFE2_SERDES.ADC_DB3_N
ADC_DB3_P: J53.Z12 ; port AFE2_SERDES.ADC_DB3_P
ADC_DB4_N: J53.Z16 ; port AFE2_SERDES.ADC_DB4_N
ADC_DB4_P: J53.Z17 ; port AFE2_SERDES.ADC_DB4_P
ADC_DB5_N: J53.Y22 ; port AFE2_SERDES.ADC_DB5_N
ADC_DB5_P: J53.Y23 ; port AFE2_SERDES.ADC_DB5_P
ADC_DB6_N: J53.Y18 ; port AFE2_SERDES.ADC_DB6_N
ADC_DB6_P: J53.Y19 ; port AFE2_SERDES.ADC_DB6_P
ADC_DB7_N: J53.Y14 ; port AFE2_SERDES.ADC_DB7_N
ADC_DB7_P: J53.Y15 ; port AFE2_SERDES.ADC_DB7_P
AFE1_ADC_ALT_SYNC_N: J53.D21 ; port AFE1_MISC.AFE1_ADC_ALT_SYNC_N
AFE1_ADC_ALT_SYNC_P: J53.D20 ; port AFE1_MISC.AFE1_ADC_ALT_SYNC_P
AFE1_ADC_SYNC_N: J53.G13 ; port AFE1_MISC.AFE1_ADC_SYNC_N
AFE1_ADC_SYNC_P: J53.G12 ; port AFE1_MISC.AFE1_ADC_SYNC_P
AFE1_AFE2_SPIA OE1: J53.E19 U32.10(OE)
AFE1_AFE2_SPIB OE2: J53.F4 U39.10(OE)
AFE1_DAC_ALT_SYNC_N: J53.D9 ; port AFE1_MISC.AFE1_DAC_ALT_SYNC_N
AFE1_DAC_ALT_SYNC_P: J53.D8 ; port AFE1_MISC.AFE1_DAC_ALT_SYNC_P
AFE1_DAC_SYNC_N: J53.F11 ; port AFE1_MISC.AFE1_DAC_SYNC_N
AFE1_DAC_SYNC_P: J53.F10 ; port AFE1_MISC.AFE1_DAC_SYNC_P
AFE1_FMC_FSPICLKA: J53.J6 ; port AFE1_MISC.AFE1_FMC_FSPICLKA
AFE1_FMC_FSPICLKB: J53.J7 ; port AFE1_MISC.AFE1_FMC_FSPICLKB
AFE1_FMC_FSPICLKC: J53.J9 ; port AFE1_MISC.AFE1_FMC_FSPICLKC
AFE1_FMC_FSPICLKD: J53.J10 ; port AFE1_MISC.AFE1_FMC_FSPICLKD
AFE1_FMC_FSPIDA: J53.J12 ; port AFE1_MISC.AFE1_FMC_FSPIDA
AFE1_FMC_FSPIDB: J53.J13 ; port AFE1_MISC.AFE1_FMC_FSPIDB
AFE1_FMC_FSPIDC: J53.J15 ; port AFE1_MISC.AFE1_FMC_FSPIDC
AFE1_FMC_FSPIDD: J53.J16 ; port AFE1_MISC.AFE1_FMC_FSPIDD
AFE1_FMC_RXADSA1PD: J53.K7 ; port AFE1_MISC.AFE1_FMC_RXADSA1PD
AFE1_FMC_RXADSA2PD: J53.K8 ; port AFE1_MISC.AFE1_FMC_RXADSA2PD
AFE1_FMC_RXADSAFAST: J53.G18 ; port AFE1_MISC.AFE1_FMC_RXADSAFAST
AFE1_FMC_RXAPD2H: J53.K10 ; port AFE1_MISC.AFE1_FMC_RXAPD2H
AFE1_FMC_RXAPD2L: J53.K11 ; port AFE1_MISC.AFE1_FMC_RXAPD2L
AFE1_FMC_RXBDSA1PD: J53.K13 ; port AFE1_MISC.AFE1_FMC_RXBDSA1PD
AFE1_FMC_RXBDSA2PD: J53.K14 ; port AFE1_MISC.AFE1_FMC_RXBDSA2PD
AFE1_FMC_RXBDSAFAST: J53.G21 ; port AFE1_MISC.AFE1_FMC_RXBDSAFAST
AFE1_FMC_RXBPD2H: J53.J18 ; port AFE1_MISC.AFE1_FMC_RXBPD2H
AFE1_FMC_RXBPD2L: J53.J19 ; port AFE1_MISC.AFE1_FMC_RXBPD2L
AFE1_FMC_RXDSASW: J53.F13 ; port AFE1_MISC.AFE1_FMC_RXDSASW
AFE1_FMC_SPIACLK: U32.20(B1) ; port AFE1_FMC_SPI.AFE1_FMC_SPIACLK
AFE1_FMC_SPIASDIO: U32.18(B2) ; port AFE1_FMC_SPI.AFE1_FMC_SPIASDIO
AFE1_FMC_SPIASDO: U32.17(B3) ; port AFE1_FMC_SPI.AFE1_FMC_SPIASDO
AFE1_FMC_SPIASEN: U32.16(B4) ; port AFE1_FMC_SPI.AFE1_FMC_SPIASEN
AFE1_FMC_SPIBCLK: U39.20(B1) ; port AFE1_FMC_SPI.AFE1_FMC_SPIBCLK
AFE1_FMC_SPIBSDIO: U39.18(B2) ; port AFE1_FMC_SPI.AFE1_FMC_SPIBSDIO
AFE1_FMC_SPIBSDO: U39.17(B3) ; port AFE1_FMC_SPI.AFE1_FMC_SPIBSDO
AFE1_FMC_SPIBSEN: U39.16(B4) ; port AFE1_FMC_SPI.AFE1_FMC_SPIBSEN
AFE1_FMC_SPICLK: J53.D11 U32.1(A1) U39.1(A1) U40.1(A1)
AFE1_FMC_SPISDIO: J53.D12 U32.3(A2) U39.3(A2) U40.3(A2)
AFE1_FMC_SPISDO: J53.D26 U32.4(A3) U39.4(A3) U40.4(A3)
AFE1_FMC_SPISEN: J53.D27 U32.5(A4) U39.5(A4) U40.5(A4)
AFE1_FMC_TXDSASW: J53.F14 ; port AFE1_MISC.AFE1_FMC_TXDSASW
AFE1_FMC_TXTDD1: J53.F16 ; port AFE1_MISC.AFE1_FMC_TXTDD1
AFE1_FMC_TXTDD2: J53.F17 ; port AFE1_MISC.AFE1_FMC_TXTDD2
AFE1_syncb0cmos: J53.E6 ; port AFE1_MISC.AFE1_syncb0cmos
AFE1_syncb1cmos: J53.E7 ; port AFE1_MISC.AFE1_syncb1cmos
AFE1_syncb2cmos: J53.E9 ; port AFE1_MISC.AFE1_syncb2cmos
AFE1_syncb3cmos: J53.E10 ; port AFE1_MISC.AFE1_syncb3cmos
AFE2_ADC_ALT_SYNC_N: J53.D18 R386.1 ; port AFE2_MISC.AFE2_ADC_ALT_SYNC_N
AFE2_ADC_ALT_SYNC_P: J53.D17 R385.2 ; port AFE2_MISC.AFE2_ADC_ALT_SYNC_P
AFE2_ADC_SYNC_N: J53.H32 ; port AFE2_MISC.AFE2_ADC_SYNC_N
AFE2_ADC_SYNC_P: J53.H31 ; port AFE2_MISC.AFE2_ADC_SYNC_P
AFE2_DAC_ALT_SYNC_N: J53.C23 ; port AFE2_MISC.AFE2_DAC_ALT_SYNC_N
AFE2_DAC_ALT_SYNC_P: J53.C22 ; port AFE2_MISC.AFE2_DAC_ALT_SYNC_P
AFE2_DAC_SYNC_N: J53.F20 ; port AFE2_MISC.AFE2_DAC_SYNC_N
AFE2_DAC_SYNC_P: J53.F19 ; port AFE2_MISC.AFE2_DAC_SYNC_P
AFE2_FMC_FSPICLKA: J53.G33 ; port AFE2_MISC.AFE2_FMC_FSPICLKA
AFE2_FMC_FSPICLKB: J53.G27 ; port AFE2_MISC.AFE2_FMC_FSPICLKB
AFE2_FMC_FSPICLKC: J53.G36 ; port AFE2_MISC.AFE2_FMC_FSPICLKC
AFE2_FMC_FSPICLKD: J53.K16 ; port AFE2_MISC.AFE2_FMC_FSPICLKD
AFE2_FMC_FSPIDA: J53.G34 ; port AFE2_MISC.AFE2_FMC_FSPIDA
AFE2_FMC_FSPIDB: J53.G28 ; port AFE2_MISC.AFE2_FMC_FSPIDB
AFE2_FMC_FSPIDC: J53.G37 ; port AFE2_MISC.AFE2_FMC_FSPIDC
AFE2_FMC_FSPIDD: J53.K17 ; port AFE2_MISC.AFE2_FMC_FSPIDD
AFE2_FMC_RXADSA1PD: J53.F7 ; port AFE2_MISC.AFE2_FMC_RXADSA1PD
AFE2_FMC_RXADSA2PD: J53.F8 ; port AFE2_MISC.AFE2_FMC_RXADSA2PD
AFE2_FMC_RXADSAFAST: J53.C18 R380.2 ; port AFE2_MISC.AFE2_FMC_RXADSAFAST
AFE2_FMC_RXAPD2H: J53.H7 ; port AFE2_MISC.AFE2_FMC_RXAPD2H
AFE2_FMC_RXAPD2L: J53.D15 ; port AFE2_MISC.AFE2_FMC_RXAPD2L
AFE2_FMC_RXBDSA1PD: J53.D14 ; port AFE2_MISC.AFE2_FMC_RXBDSA1PD
AFE2_FMC_RXBDSA2PD: J53.C14 ; port AFE2_MISC.AFE2_FMC_RXBDSA2PD
AFE2_FMC_RXBDSAFAST: J53.C15 ; port AFE2_MISC.AFE2_FMC_RXBDSAFAST
AFE2_FMC_RXBPD2H: J53.H8 ; port AFE2_MISC.AFE2_FMC_RXBPD2H
AFE2_FMC_RXBPD2L: J53.C10 ; port AFE2_MISC.AFE2_FMC_RXBPD2L
AFE2_FMC_RXDSASW: J53.J21 ; port AFE2_MISC.AFE2_FMC_RXDSASW
AFE2_FMC_SPIACLK: U32.15(B5) ; port AFE2_FMC_SPI.AFE2_FMC_SPIACLK
AFE2_FMC_SPIASDIO: U32.14(B6) ; port AFE2_FMC_SPI.AFE2_FMC_SPIASDIO
AFE2_FMC_SPIASDO: U32.13(B7) ; port AFE2_FMC_SPI.AFE2_FMC_SPIASDO
AFE2_FMC_SPIASEN: U32.12(B8) ; port AFE2_FMC_SPI.AFE2_FMC_SPIASEN
AFE2_FMC_SPIBCLK: U39.15(B5) ; port AFE2_FMC_SPI.AFE2_FMC_SPIBCLK
AFE2_FMC_SPIBSDIO: U39.14(B6) ; port AFE2_FMC_SPI.AFE2_FMC_SPIBSDIO
AFE2_FMC_SPIBSDO: U39.13(B7) ; port AFE2_FMC_SPI.AFE2_FMC_SPIBSDO
AFE2_FMC_SPIBSEN: U39.12(B8) ; port AFE2_FMC_SPI.AFE2_FMC_SPIBSEN
AFE2_FMC_SPICLK: J53.E12 U32.6(A5) U39.6(A5) U40.6(A5)
AFE2_FMC_SPISDIO: J53.E13 U32.7(A6) U39.7(A6) U40.7(A6)
AFE2_FMC_SPISDO: J53.E15 U32.8(A7) U39.8(A7) U40.8(A7)
AFE2_FMC_SPISEN: J53.E16 U32.9(A8) U39.9(A8) U40.9(A8)
AFE2_FMC_TXDSASW: J53.J22 ; port AFE2_MISC.AFE2_FMC_TXDSASW
AFE2_FMC_TXTDD1: J53.E18 ; port AFE2_MISC.AFE2_FMC_TXTDD1
AFE2_FMC_TXTDD2: J53.K19 ; port AFE2_MISC.AFE2_FMC_TXTDD2
AFE2_syncb0cmos: J53.E3 ; port AFE2_MISC.AFE2_syncb0cmos
AFE2_syncb1cmos: J53.E2 ; port AFE2_MISC.AFE2_syncb1cmos
AFE2_syncb2cmos: J53.C27 ; port AFE2_MISC.AFE2_syncb2cmos
AFE2_syncb3cmos: J53.C26 ; port AFE2_MISC.AFE2_syncb3cmos
CAR_SYSREFM: J53.G10 ; port FMC_LMK.CAR_SYSREFM
CAR_SYSREFP: J53.G9 ; port FMC_LMK.CAR_SYSREFP
CLK0_M2C_N: J53.H5 ; port FMC_LMK.CLK0_M2C_N
CLK0_M2C_P: J53.H4 ; port FMC_LMK.CLK0_M2C_P
CLK1_M2C_N: J53.G3 ; port FMC_LMK.CLK1_M2C_N
CLK1_M2C_P: J53.G2 ; port FMC_LMK.CLK1_M2C_P
CLK_LAO_0M: J53.G7 ; port FMC_LMK.CLK_LAO_0M
CLK_LAO_0P: J53.G6 ; port FMC_LMK.CLK_LAO_0P
DAC_DA0_N: J53.C3 ; port AFE1_SERDES.DAC_DA0_N
DAC_DA0_P: J53.C2 ; port AFE1_SERDES.DAC_DA0_P
DAC_DA1_N: J53.A23 ; port AFE1_SERDES.DAC_DA1_N
DAC_DA1_P: J53.A22 ; port AFE1_SERDES.DAC_DA1_P
DAC_DA2_N: J53.A27 ; port AFE1_SERDES.DAC_DA2_N
DAC_DA2_P: J53.A26 ; port AFE1_SERDES.DAC_DA2_P
DAC_DA3_N: J53.A31 ; port AFE1_SERDES.DAC_DA3_N
DAC_DA3_P: J53.A30 ; port AFE1_SERDES.DAC_DA3_P
DAC_DA4_N: J53.A35 ; port AFE1_SERDES.DAC_DA4_N
DAC_DA4_P: J53.A34 ; port AFE1_SERDES.DAC_DA4_P
DAC_DA5_N: J53.A39 ; port AFE1_SERDES.DAC_DA5_N
DAC_DA5_P: J53.A38 ; port AFE1_SERDES.DAC_DA5_P
DAC_DA6_N: J53.B37 ; port AFE1_SERDES.DAC_DA6_N
DAC_DA6_P: J53.B36 ; port AFE1_SERDES.DAC_DA6_P
DAC_DA7_N: J53.B33 ; port AFE1_SERDES.DAC_DA7_N
DAC_DA7_P: J53.B32 ; port AFE1_SERDES.DAC_DA7_P
DAC_DB0_N: J53.Z9 ; port AFE2_SERDES.DAC_DB0_N
DAC_DB0_P: J53.Z8 ; port AFE2_SERDES.DAC_DB0_P
DAC_DB1_N: J53.Y7 ; port AFE2_SERDES.DAC_DB1_N
DAC_DB1_P: J53.Y6 ; port AFE2_SERDES.DAC_DB1_P
DAC_DB2_N: J53.B25 ; port AFE2_SERDES.DAC_DB2_N
DAC_DB2_P: J53.B24 ; port AFE2_SERDES.DAC_DB2_P
DAC_DB3_N: J53.Z25 ; port AFE2_SERDES.DAC_DB3_N
DAC_DB3_P: J53.Z24 ; port AFE2_SERDES.DAC_DB3_P
DAC_DB4_N: J53.B29 ; port AFE2_SERDES.DAC_DB4_N
DAC_DB4_P: J53.B28 ; port AFE2_SERDES.DAC_DB4_P
DAC_DB5_N: J53.Y31 ; port AFE2_SERDES.DAC_DB5_N
DAC_DB5_P: J53.Y30 ; port AFE2_SERDES.DAC_DB5_P
DAC_DB6_N: J53.Z29 ; port AFE2_SERDES.DAC_DB6_N
DAC_DB6_P: J53.Z28 ; port AFE2_SERDES.DAC_DB6_P
DAC_DB7_N: J53.Y27 ; port AFE2_SERDES.DAC_DB7_N
DAC_DB7_P: J53.Y26 ; port AFE2_SERDES.DAC_DB7_P
E_SCL: J53.C30 J54.2 U9.6(SCL)
E_SDA: J53.C31 J54.1 U9.5(SDA)
EE_ADDR0_RX: J53.C34 U9.1(A0)
EE_ADDR1_RX: J53.D35 U9.2(A1)
FMC_LMK_CS: J53.H17 U40.12(B8) ; port FMC_LMK_CS
FMC_LMK_SCK: J53.G15 U40.15(B5) ; port FMC_LMK_SCK
FMC_LMK_SDIO: J53.G16 U40.14(B6) ; port FMC_LMK_SDIO
FMC_LMK_SDO: J53.H16 U40.13(B7) ; port FMC_LMK_SDO
FMC_LMX_CS: U40.16(B4) ; port FMC_LMX_CS
FMC_LMX_SCK: U40.20(B1) ; port FMC_LMX_SCK
FMC_LMX_SDIO: U40.18(B2) ; port FMC_LMX_SDIO
FMC_LMX_SDO: U40.17(B3) ; port FMC_LMX_SDO
FMC_SCL: J53.G22 U63.3(A2)
FMC_SDA: J53.F5 U63.2(A1)
FMC_TCK: J53.D29 ; port FMC_JTAG.FMC_TCK
FMC_TDI: J53.D30 ; port FMC_JTAG.FMC_TDI
FMC_TDO: J53.D31 ; port FMC_JTAG.FMC_TDO
FMC_TMS: J53.D33 ; port FMC_JTAG.FMC_TMS
FMC_TRSTB: J53.D34 ; port FMC_JTAG.FMC_TRSTB
FPGA_CLK1_N: J53.K5 ; port FMC_LMK.FPGA_CLK1_N
FPGA_CLK1_P: J53.K4 ; port FMC_LMK.FPGA_CLK1_P
FPGA_CLK2_N: J53.J3 ; port FMC_LMK.FPGA_CLK2_N
FPGA_CLK2_P: J53.J2 ; port FMC_LMK.FPGA_CLK2_P
GBTCLK1_M2C_N: J53.B21 ; port FMC_LMK.GBTCLK1_M2C_N
GBTCLK1_M2C_P: J53.B20 ; port FMC_LMK.GBTCLK1_M2C_P
GPIO0: J53.H28 TP54.1
GPIO1: J53.H29 TP55.1
GTX_CLKM: J53.D5 ; port FMC_LMK.GTX_CLKM
GTX_CLKP: J53.D4 ; port FMC_LMK.GTX_CLKP
I2C_SCL: U63.6(B2) ; port I2C_SCL
I2C_SDA: U63.7(B1) ; port I2C_SDA
LMK_SYNC: J53.K22 ; port FMC_LMK.LMK_SYNC
NB7_RESET: R387.1 ; port FMC_LMK.NB7_RESET
PG_C2M: J53.D1 R382.1
PG_M2C: J53.F1 R381.1
SEL_SPI: U40.10(OE) ; port SEL_SPI
VADJ: J53.E39 J53.F40 J53.G39 J53.H40 R381.2
VIO_B_M2C: J53.J39 J53.K40 TP2.1
VREF_A_M2C: J53.H1 TP3.1
VREF_B_M2C: J53.K1 TP4.1
NetD7_2: D7.2(K) R379.2
NetD8_2: D8.2(K) R383.2
NetD9_2: D9.2(K) R382.2
NetD10_2: D10.2(K) R388.2
NetJ53_H2: J53.H2 R384.2
NetJ53_H19: J53.H19 R387.2
NetJ53_Z1: J53.Z1 TP5.1
NetQ1_1: Q1.1(B) R380.1
NetQ1_3: Q1.3(C) R379.1
NetQ2_1: Q2.1(B) R385.1
NetQ2_3: Q2.3(C) R383.1
NetQ3_1: Q3.1(B) R386.2
NetQ3_3: Q3.3(C) R388.1
NetR496_1: R496.1 U63.5(OE)

Not connected (* = marked no-connect by the designer): J53 B1 B40 C11 C19 D23 D24 E21 E22 E24 E25 E27 E28 E30 E31 E33 E34 E36 E37 F2 F22 F23 F25 F26 F28 F29 F31 F32 F34 F35 F37 F38 G19 G24 G25 G30 G31 H10 H11 H13 H14 H20 H22 H23 H25 H26 H34 H35 H37 H38 J24 J25 J27 J28 J30 J31 J33 J34 J36 J37 K20 K23 K25 K26 K28 K29 K31 K32 K34 K35 K37 K38 L1 L2 L3 L4 L5 L6 L8 L9 L10 L11 L12 L13 L14 L15 L16 L17 L18 L19 L20 L21 L22 L23 L24 L25 L26 L27 L28 L29 L32 L33 L36 L37 L40 M2 M3 M4 M5 M6 M7 M8 M9 M10 M11 M12 M13 M14 M15 M16 M17 M18 M19 M20 M21 M22 M23 M24 M25 M26 M27 M28 M30 M31 M34 M35 M38 M39 Y1 Y2 Y3 Y34 Y35 Y38 Y39 Z4 Z5 Z6 Z20 Z21 Z32 Z33 Z36 Z37 Z40; U9 7(NC)

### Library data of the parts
C197 C202 C203 C214 C215 C217 C579 C580 = C0603C104J3RACTU: CAP, CERM, 0.1uF, 25V, +/-5%, X7R, 0603; Manufacturer: Kemet; Polarized: N; TaMax_C: 125; TaMin_C: -55; Tolerance_%: 5; VDC_V: 25; Cap_F: 0.0000001; CompType: Capacitor; Value1: Unknown; U/M: EA
C515 = CMP-0006211-2: CAP, CERM, 0.1 uF, 16 V, +/- 10%, Unknown, 0402; Manufacturer: AT Ceramics; TaMin_C: -55°C; Polarized: N; SizeAreaWB_mm2: 3; U/M: EA; Value: 0.1uF; TaMax_C: 125°C; SizeZ_mm: 0.65; SizeX_mm: 1; SizeY_mm: 0.5; Cap_Case: 0402; Value2: 16V; Cap_F: 100nF; AEC Category: Q200
D7-D10 = CMP-0002976-2: LED, Green, SMD; Manufacturer: Panasonic; Io_A: 5mA; Vr_V: 4V; Tjmax_C: 85°C; Value1: W; U/M: EA; Ir_A: 10µA; Vf_V: 1.95V
J53 = ASP-184330-01: 14 ROW .050 PITCH TERMINAL ARRAY ASM.; Manufacturer: SAMTEC
J54 = 342-10-104-00-591000: Header, 100mil, 4x1, Gold, TH; Manufacturer: Mill-Max; SymbolCreator: a0412235; Green_Lifecycle: Active; Green_REACh: Passed
Q1-Q3 = CMP-0000485-2: Transistor, NPN, 50 V, 0.1 A, AEC-Q101, SOT-416; Manufacturer: ON Semiconductor; TaMax_C: 150°C; Value2: 60; Value1: 0.1 A; Vcesat1_V: 2.5dV; SizeX_mm: 1.6; TaMin_C: -55°C; IcRated_A: 1dA; CompType: BJT; SizeZ_mm: 0.95; AEC Qualified: Y; Value: 50 V; SizeArea_mm2: 2.56; NPN: 1; Vceo_V: 50V; PNP: 0; AEC Category: Q101; SizeAreaWB_mm2: 6.76; U/M: EA
R379 R382 R383 R388 = RC0603FR-07604RL: RES, 604, 1%, 0.1 W, 0603; Manufacturer: Yageo America; CompType: Resistor; Value: 604; Value_Code: 604R; Tolerance_%: 1; Power_W: 0.1; Value2: 0.1W; VDC_V: 150; TempCo: 200 ppm/C; SizeArea_mm2: 1.28; SizeX_mm: 1.6; SizeY_mm: 0.8; EIA_Code: E96; U/M: EA; AEC Category: Q200; Green_Lifecycle: Active; Green_REACh: Passed
R380 R384-R387 = ERJ-2GE0R00X: RES, 0, 5%, 0.063 W, 0402; Manufacturer: Panasonic; CompType: Resistor; Value: 0; Value_Code: 0000; Tolerance_%: 5; Power_W: 0.063; Value2: 0.063W; VDC_V: 50; TempCo: 600 ppm/C; SizeArea_mm2: 0.5; SizeX_mm: 1; SizeZ_mm: 0.6; EIA_Code: E24; U/M: EA; AEC Category: Q200; Green_Lifecycle: Active; Green_REACh: Passed
R381 = CRCW06034K99FKEA: RES, 4.99 k, 1%, 0.1 W, 0603; Manufacturer: Vishay-Dale; CompType: Resistor; Value: 4.99k; Res_ohm: 4990; Value_Code: 4k99; Tolerance_%: 1; Power_W: 0.1; Value2: 0.1W; VDC_V: 75; TempCo: 100 ppm/C; SizeArea_mm2: 1.28; SizeX_mm: 1.6; SizeY_mm: 0.8; EIA_Code: E96; U/M: EA; AEC Category: Q200; Green_Lifecycle: Active; Green_REACh: Passed
R496 = CRCW060310K0JNEA: RES, 10 k, 5%, 0.1 W, 0603; Manufacturer: Vishay-Dale; CompType: Resistor; Value: 10k; Res_ohm: 10000; Value_Code: 10k0; Tolerance_%: 5; Power_W: 0.1; Value2: 0.1W; VDC_V: 75; TempCo: 200 ppm/C; SizeArea_mm2: 1.28; SizeX_mm: 1.6; SizeY_mm: 0.8; SizeZ_mm: 1; EIA_Code: E24; U/M: EA; AEC Category: Q200
TP1-TP7 = 5000: Test Point, Miniature, Red, TH; Manufacturer: Keystone; CompType: Test Point Loop; ContactFinish: Silver; Green_Lifecycle: Active; Green_REACh: Passed
TP54 TP55 = TP-025-SMT: Test Point, O.025"; Manufacturer: STD; Value: STD
U9 = CMP-0005259-2: 64K I2C Smart Serial EEPROM, SOIC-8; Manufacturer: Microchip
U32 U39 U40 = CMP-0067446-2: 8-Bit Bidirectional Voltage-Level Shifter For Open-Drain And Push-Pull Application, RGY0020A (VQFN-20); Alternate Manufacturer: Texas Instruments; Green_Lifecycle: Active; SizeAreaWB_mm2: 24.75; Green_REACh: Passed; U/M: EA; SizeZ_mm: 1.0; SizeX_mm: 3.5; SizeY_mm: 4.5; SizeArea_mm2: 15.75; CompType: IC
U63 = CMP-0074354-1: 2-Bit Bidirectional Voltage-Level Shifter for Open-Drain and Push-Pull Application, DQE0008A (X2SON-8); Alternate Manufacturer: Texas Instruments; SizeAreaWB_mm2: 4.8; U/M: EA; SizeZ_mm: 0.4; SizeX_mm: 1.0; SizeY_mm: 1.4; CompType: IC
